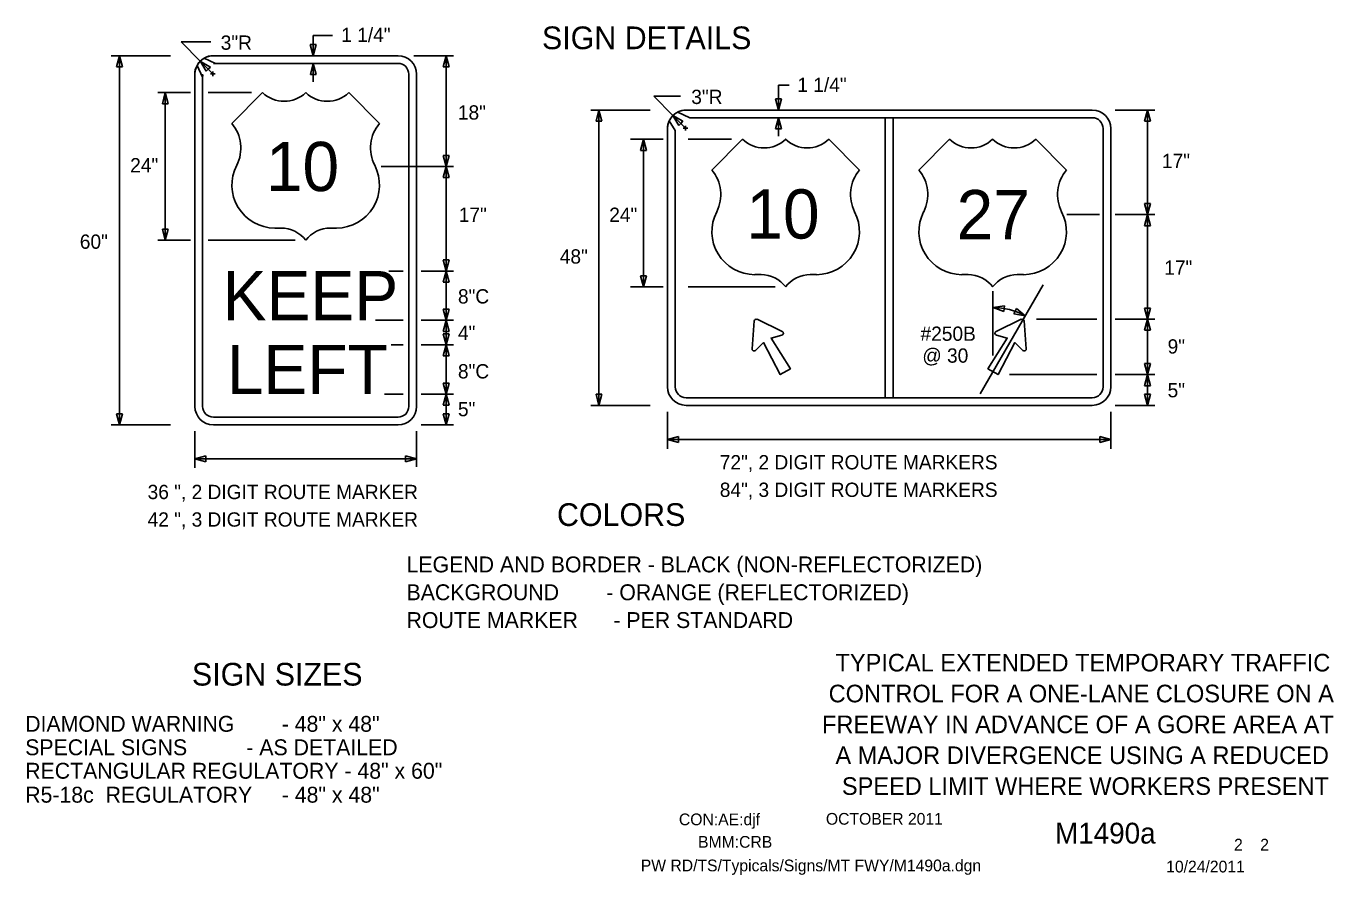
# Model space of a CAD drawing. Extents: x 16284 to 18465, y 5417 to 6974.
# Drawn here: x 17775 to 18465, y 5932 to 6380 of the extents above; entities that cross this region are included whole.
import ezdxf

# ---------------------------------------------------------------- set-up
doc = ezdxf.new("R2010")
doc.units = 0
for name, color, linetype in [('BORDER', 7, 'Continuous'), ('BORDER_SIGNAL_WO', 7, 'Continuous'), ('TRAFFIC_SIGNS_PR', 7, 'Continuous'), ('TYPICAL_EX', 7, 'Continuous'), ('TYPICAL_TEXT_DIMEN_PR', 7, 'Continuous')]:
    doc.layers.add(name, color=color, linetype=linetype)

msp = doc.modelspace()

# ---------------------------------------------------------------- linework, layer by layer
at = {"layer": 'TRAFFIC_SIGNS_PR'}
for p, q in [((17866.33, 6360.97), (17865.33, 6359.46)), ((17865.36, 6359.39), (17868.23, 6353.35)), ((17875.12, 6360.53), (17869.02, 6363.27)), ((17873.92, 6364.59), (17971.42, 6364.59)), ((17971.42, 6360.53), (17873.92, 6360.53)), ((17864.17, 6179.34), (17864.17, 6354.84)), ((17868.23, 6354.84), (17868.23, 6179.34)), ((17977.1, 6179.34), (17977.1, 6354.84)), ((17981.17, 6354.84), (17981.17, 6179.34)), ((18125.39, 6331.84), (18119.16, 6334.86)), ((18123.44, 6335.89), (18337.94, 6335.89)), ((18123.44, 6335.89), (18337.94, 6335.89)), ((18125.38, 6331.83), (18228.66, 6331.83)), ((18337.94, 6331.83), (18125.38, 6331.83)), ((18228.66, 6331.83), (18228.66, 6183.95)), ((18232.72, 6331.83), (18232.72, 6183.95)), ((18232.72, 6331.83), (18337.94, 6331.83)), ((18113.69, 6326.14), (18113.69, 6189.64)), ((18113.69, 6189.64), (18113.69, 6326.14)), ((18114.61, 6330.15), (18117.74, 6325.11)), ((18117.75, 6325.09), (18117.75, 6189.64)), ((18117.75, 6325.09), (18117.75, 6189.64)), ((18343.62, 6326.14), (18343.62, 6280.39)), ((18343.63, 6189.64), (18343.63, 6326.14)), ((18347.69, 6326.14), (18347.69, 6189.64)), ((18347.69, 6326.14), (18347.69, 6189.64)), ((18343.62, 6280.39), (18343.62, 6189.64)), ((18158.29, 6209.75), (18159.44, 6224.47)), ((18160.95, 6225.34), (18174.27, 6218.98)), ((18300.42, 6225.34), (18287.11, 6218.98)), ((18303.08, 6209.75), (18301.94, 6224.47)), ((18123.44, 6183.95), (18337.94, 6183.95)), ((18123.44, 6179.89), (18337.94, 6179.89)), ((18337.94, 6179.89), (18123.44, 6179.89)), ((17873.92, 6173.65), (17971.42, 6173.65)), ((17971.42, 6169.59), (17873.92, 6169.59))]:
    msp.add_line(p, q, dxfattribs=at)
for points in [[(18125.38, 6331.83), (18125.36, 6331.84)], [(18117.74, 6325.11), (18117.75, 6325.09)], [(18174.1, 6217.01), (18168.38, 6215.43), (18178.6, 6199.26), (18173.2, 6196.14), (18164.31, 6213.08), (18160.08, 6208.91)], [(18287.27, 6217.01), (18292.99, 6215.43), (18282.78, 6199.26), (18288.17, 6196.14), (18297.07, 6213.08), (18301.29, 6208.91)]]:
    msp.add_lwpolyline(points, dxfattribs=at)
msp.add_lwpolyline([(18228.66, 6331.83), (18232.72, 6331.83), (18232.72, 6183.95), (18228.66, 6183.95)], close=True, dxfattribs=at)
for centre, radius, start, end in [((17871.2, 6355.43), 7.06, 145.86811, 184.82317), ((17873.92, 6354.84), 9.75, 90, 180), ((17873.33, 6357.01), 7.6, 85.58319, 124.53531), ((17874.52, 6364.95), 4.47, 262.2432, 277.7568), ((17971.42, 6354.84), 9.75, 0, 90), ((17971.42, 6354.84), 5.69, 0, 90), ((17862.77, 6354.1), 5.51, 352.24294, 7.75653), ((18123.44, 6326.14), 9.75, 90, 180), ((18123.44, 6326.14), 9.75, 90, 180), ((18122.76, 6329.33), 6.6, 84.11162, 123.06374), ((18124.38, 6339.01), 7.24, 277.81035, 278.05403), ((18337.94, 6326.14), 9.75, 0, 90), ((18337.94, 6326.14), 9.75, 0, 90), ((18337.94, 6326.14), 5.69, 0, 89.99421), ((18337.94, 6326.14), 5.69, 0, 90), ((18119.82, 6326.85), 6.17, 147.60925, 186.56283), ((18160.5, 6224.38), 1.06, 64.48226, 175.51774), ((18300.88, 6224.38), 1.06, 4.48226, 115.51774), ((18173.81, 6218.02), 1.06, 285.9885, 64.48226), ((18287.56, 6218.02), 1.06, 115.51774, 254.0115), ((18159.35, 6209.67), 1.06, 175.51775, 314.01151), ((18302.03, 6209.67), 1.06, 225.98849, 4.48225), ((18123.44, 6189.64), 9.75, 180, 270), ((18123.44, 6189.64), 9.75, 180, 270), ((18123.44, 6189.64), 5.69, 180, 270), ((18123.44, 6189.64), 5.69, 180, 270), ((18337.94, 6189.64), 9.75, 270, 0), ((18337.94, 6189.64), 5.69, 270, 0), ((18337.94, 6189.64), 9.75, 270, 0), ((18337.94, 6189.64), 5.69, 270, 0), ((17873.92, 6179.34), 9.75, 180, 270), ((17873.92, 6179.34), 5.69, 180, 270), ((17971.42, 6179.34), 5.69, 270, 0), ((17971.42, 6179.34), 9.75, 270, 0)]:
    msp.add_arc(centre, radius, start, end, dxfattribs=at)
at = {"layer": 'TYPICAL_EX'}
for p, q in [((17883.67, 6328.84), (17899.92, 6345.09)), ((17961.67, 6328.84), (17945.42, 6345.09)), ((18137.05, 6304.23), (18153.3, 6320.48)), ((18215.05, 6304.23), (18198.8, 6320.48)), ((18246.33, 6304.23), (18262.58, 6320.48)), ((18324.33, 6304.23), (18308.08, 6320.48)), ((17906.39, 6273.55), (17909.64, 6273.55)), ((17938.94, 6273.55), (17935.69, 6273.55)), ((18159.78, 6248.94), (18163.03, 6248.94)), ((18192.32, 6248.94), (18189.07, 6248.94)), ((18269.05, 6248.94), (18272.3, 6248.94)), ((18301.6, 6248.94), (18298.35, 6248.94))]:
    msp.add_line(p, q, dxfattribs=at)
for centre, radius, start, end in [((17911.29, 6356.93), 16.42, 226.14041, 313.85958), ((17934.04, 6356.93), 16.42, 226.14042, 313.85959), ((17868.26, 6315.83), 20.16, 333.09768, 40.19361), ((17977.07, 6315.83), 20.16, 139.80639, 206.90233), ((18164.68, 6332.32), 16.42, 226.14041, 313.85958), ((18187.42, 6332.32), 16.42, 226.14042, 313.85959), ((18273.95, 6332.32), 16.42, 226.14041, 313.85958), ((18296.7, 6332.32), 16.42, 226.14042, 313.85959), ((17906.43, 6296.27), 22.73, 152.6698, 269.90132), ((17938.9, 6296.27), 22.73, 270.09868, 27.3302), ((18121.65, 6291.22), 20.16, 333.09768, 40.19361), ((18230.45, 6291.22), 20.16, 139.80639, 206.90233), ((18230.93, 6291.22), 20.16, 333.09768, 40.19361), ((18339.73, 6291.22), 20.16, 139.80639, 206.90233), ((18159.82, 6271.66), 22.73, 152.6698, 269.90132), ((18192.28, 6271.66), 22.73, 270.09868, 27.3302), ((18269.09, 6271.66), 22.73, 152.6698, 269.90132), ((18301.56, 6271.66), 22.73, 270.09868, 27.3302), ((17909.68, 6257.27), 16.28, 37.1038, 90.13853), ((17935.65, 6257.27), 16.28, 89.86147, 142.8962), ((18163.07, 6232.66), 16.28, 37.1038, 90.13853), ((18189.03, 6232.66), 16.28, 89.86147, 142.8962), ((18272.35, 6232.66), 16.28, 37.1038, 90.13853), ((18298.31, 6232.66), 16.28, 89.86147, 142.8962)]:
    msp.add_arc(centre, radius, start, end, dxfattribs=at)
at = {"layer": 'TYPICAL_TEXT_DIMEN_PR'}
for p, q in [((17926.64, 6375.35), (17926.64, 6364.59)), ((17926.64, 6375.35), (17936.74, 6375.35)), ((17872.54, 6371.87), (17856.88, 6371.87)), ((17856.88, 6371.87), (17867.12, 6361.64)), ((17926.64, 6364.59), (17925.07, 6370.45)), ((17925.07, 6370.45), (17926.64, 6370.45)), ((17926.64, 6370.45), (17928.21, 6370.45)), ((17928.21, 6370.45), (17926.64, 6364.59)), ((17851.34, 6364.59), (17820.04, 6364.59)), ((17822.81, 6358.73), (17824.38, 6364.59)), ((17824.38, 6358.73), (17822.81, 6358.73)), ((17824.38, 6364.59), (17824.38, 6169.59)), ((17824.38, 6364.59), (17825.95, 6358.73)), ((17825.95, 6358.73), (17824.38, 6358.73)), ((17867.12, 6361.64), (17873.67, 6355.08)), ((17870.15, 6356.38), (17867.12, 6361.64)), ((17867.12, 6361.64), (17872.37, 6358.6)), ((17872.37, 6358.6), (17871.26, 6357.49)), ((17925.12, 6354.67), (17926.69, 6360.53)), ((17926.69, 6360.53), (17926.69, 6350.78)), ((17926.69, 6360.53), (17928.26, 6354.67)), ((17979.71, 6364.59), (18000.67, 6364.59)), ((17995.2, 6358.73), (17996.77, 6364.59)), ((17996.77, 6358.73), (17995.2, 6358.73)), ((17996.77, 6364.59), (17996.77, 6306.09)), ((17996.77, 6364.59), (17998.34, 6358.73)), ((17998.34, 6358.73), (17996.77, 6358.73)), ((17871.26, 6357.49), (17870.15, 6356.38)), ((17872.47, 6355.08), (17874.88, 6355.08)), ((17873.67, 6353.87), (17873.67, 6356.29)), ((17926.69, 6354.67), (17925.12, 6354.67)), ((17928.26, 6354.67), (17926.69, 6354.67)), ((17861.79, 6345.09), (17844.67, 6345.09)), ((17846.99, 6339.23), (17848.56, 6345.09)), ((17848.56, 6345.09), (17848.56, 6267.09)), ((17848.56, 6345.09), (17850.13, 6339.23)), ((17894.03, 6345.09), (17871.16, 6345.09)), ((18172.3, 6349.04), (18172.3, 6335.89)), ((18172.3, 6349.04), (18177.82, 6349.04)), ((17848.56, 6339.23), (17846.99, 6339.23)), ((17850.13, 6339.23), (17848.56, 6339.23)), ((18120.58, 6343.18), (18106.4, 6343.18)), ((18106.4, 6343.18), (18116.55, 6333.03)), ((18172.3, 6335.89), (18170.72, 6341.75)), ((18170.72, 6341.75), (18172.3, 6341.75)), ((18172.3, 6341.75), (18173.87, 6341.75)), ((18173.87, 6341.75), (18172.3, 6335.89)), ((18104.46, 6335.89), (18073.16, 6335.89)), ((18075.93, 6330.03), (18077.5, 6335.89)), ((18077.5, 6335.89), (18077.5, 6179.89)), ((18077.5, 6335.89), (18079.07, 6330.03)), ((18116.55, 6333.03), (18123.2, 6326.38)), ((18119.58, 6327.77), (18116.55, 6333.03)), ((18116.55, 6333.03), (18121.81, 6329.99)), ((18170.77, 6325.97), (18172.34, 6331.83)), ((18170.77, 6325.97), (18172.34, 6331.83)), ((18172.34, 6331.83), (18172.34, 6322.08)), ((18172.34, 6331.83), (18173.92, 6325.97)), ((18172.34, 6331.83), (18173.92, 6325.97)), ((18350.06, 6335.89), (18371.02, 6335.89)), ((18365.55, 6330.03), (18367.12, 6335.89)), ((18367.12, 6335.89), (18367.12, 6280.64)), ((18367.12, 6335.89), (18368.69, 6330.03)), ((18077.5, 6330.03), (18075.93, 6330.03)), ((18079.07, 6330.03), (18077.5, 6330.03)), ((18120.7, 6328.88), (18119.58, 6327.77)), ((18121.81, 6329.99), (18120.7, 6328.88)), ((18121.99, 6326.38), (18124.41, 6326.38)), ((18123.2, 6325.17), (18123.2, 6327.59)), ((18172.34, 6325.97), (18170.77, 6325.97)), ((18172.34, 6325.97), (18170.77, 6325.97)), ((18173.92, 6325.97), (18172.34, 6325.97)), ((18173.92, 6325.97), (18172.34, 6325.97)), ((18367.12, 6330.03), (18365.55, 6330.03)), ((18368.69, 6330.03), (18367.12, 6330.03)), ((18111.31, 6320.48), (18094.19, 6320.48)), ((18099.48, 6314.62), (18101.06, 6320.48)), ((18101.06, 6320.48), (18101.06, 6242.48)), ((18101.06, 6320.48), (18102.63, 6314.62)), ((18147.42, 6320.48), (18124.54, 6320.48)), ((17996.77, 6306.09), (17995.2, 6311.95)), ((17995.2, 6311.95), (17996.77, 6311.95)), ((17996.77, 6311.95), (17998.34, 6311.95)), ((17998.34, 6311.95), (17996.77, 6306.09)), ((18101.06, 6314.62), (18099.48, 6314.62)), ((18102.63, 6314.62), (18101.06, 6314.62)), ((17962.56, 6306.09), (18000.67, 6306.09)), ((17995.2, 6300.23), (17996.77, 6306.09)), ((17996.77, 6306.09), (17996.77, 6250.84)), ((17996.77, 6306.09), (17998.34, 6300.23)), ((17996.77, 6300.23), (17995.2, 6300.23)), ((17998.34, 6300.23), (17996.77, 6300.23)), ((18367.12, 6280.64), (18365.55, 6286.5)), ((18365.55, 6286.5), (18367.12, 6286.5)), ((18367.12, 6286.5), (18368.69, 6286.5)), ((18368.69, 6286.5), (18367.12, 6280.64)), ((18324.5, 6280.64), (18341.65, 6280.64)), ((18350.06, 6280.64), (18371.02, 6280.64)), ((18365.55, 6274.78), (18367.12, 6280.64)), ((18367.12, 6280.64), (18367.12, 6225.39)), ((18367.12, 6280.64), (18368.69, 6274.78)), ((17848.56, 6267.09), (17846.99, 6272.95)), ((17846.99, 6272.95), (17848.56, 6272.95)), ((17848.56, 6272.95), (17850.13, 6272.95)), ((17850.13, 6272.95), (17848.56, 6267.09)), ((18367.12, 6274.78), (18365.55, 6274.78)), ((18368.69, 6274.78), (18367.12, 6274.78)), ((17861.79, 6267.09), (17844.67, 6267.09)), ((17917.16, 6267.09), (17871.16, 6267.09)), ((17996.77, 6250.84), (17995.2, 6256.7)), ((17995.2, 6256.7), (17996.77, 6256.7)), ((17996.77, 6256.7), (17998.34, 6256.7)), ((17998.34, 6256.7), (17996.77, 6250.84)), ((17966.49, 6250.84), (17974.17, 6250.84)), ((17983.54, 6250.84), (18000.67, 6250.84)), ((17995.2, 6244.98), (17996.77, 6250.84)), ((17996.77, 6250.84), (17996.77, 6224.84)), ((17996.77, 6250.84), (17998.34, 6244.98)), ((18101.06, 6242.48), (18099.48, 6248.34)), ((18099.48, 6248.34), (18101.06, 6248.34)), ((18101.06, 6248.34), (18102.63, 6248.34)), ((18102.63, 6248.34), (18101.06, 6242.48)), ((17996.77, 6244.98), (17995.2, 6244.98)), ((17998.34, 6244.98), (17996.77, 6244.98)), ((18111.31, 6242.48), (18094.19, 6242.48)), ((18170.54, 6242.48), (18124.54, 6242.48)), ((18278.72, 6185.99), (18311.96, 6243.58)), ((18285.48, 6206.15), (18285.48, 6240.14)), ((17996.77, 6224.84), (17995.2, 6230.7)), ((17995.2, 6230.7), (17996.77, 6230.7)), ((17996.77, 6230.7), (17998.34, 6230.7)), ((17998.34, 6230.7), (17996.77, 6224.84)), ((18285.51, 6231.59), (18291.5, 6232.55)), ((18291.17, 6229.42), (18285.51, 6231.59)), ((18291.34, 6230.98), (18291.17, 6229.42)), ((18291.5, 6232.55), (18291.34, 6230.98)), ((18296.49, 6228.26), (18297.17, 6229.68)), ((18302.46, 6227.13), (18296.49, 6228.26)), ((18297.17, 6229.68), (18297.86, 6231.09)), ((18297.86, 6231.09), (18302.46, 6227.13)), ((18367.12, 6225.39), (18365.55, 6231.25)), ((18365.55, 6231.25), (18367.12, 6231.25)), ((18367.12, 6231.25), (18368.69, 6231.25)), ((18368.69, 6231.25), (18367.12, 6225.39)), ((17959.48, 6224.84), (17974.17, 6224.84)), ((17983.54, 6224.84), (18000.67, 6224.84)), ((17995.2, 6218.98), (17996.77, 6224.84)), ((17996.77, 6224.84), (17996.77, 6211.84)), ((17996.77, 6224.84), (17998.34, 6218.98)), ((18308.43, 6225.39), (18340.3, 6225.39)), ((18350.06, 6225.39), (18371.02, 6225.39)), ((18365.55, 6219.53), (18367.12, 6225.39)), ((18367.12, 6225.39), (18367.12, 6196.14)), ((18367.12, 6225.39), (18368.69, 6219.53)), ((17996.77, 6218.98), (17995.2, 6218.98)), ((17996.77, 6211.84), (17995.2, 6217.7)), ((17995.2, 6217.7), (17996.77, 6217.7)), ((17998.34, 6218.98), (17996.77, 6218.98)), ((17996.77, 6217.7), (17998.34, 6217.7)), ((17998.34, 6217.7), (17996.77, 6211.84)), ((18367.12, 6219.53), (18365.55, 6219.53)), ((18368.69, 6219.53), (18367.12, 6219.53)), ((17967.83, 6211.84), (17974.17, 6211.84)), ((17983.54, 6211.84), (18000.67, 6211.84)), ((17995.2, 6205.98), (17996.77, 6211.84)), ((17996.77, 6211.84), (17996.77, 6185.84)), ((17996.77, 6211.84), (17998.34, 6205.98)), ((17996.77, 6205.98), (17995.2, 6205.98)), ((17998.34, 6205.98), (17996.77, 6205.98)), ((18367.12, 6196.14), (18365.55, 6202)), ((18365.55, 6202), (18367.12, 6202)), ((18367.12, 6202), (18368.69, 6202)), ((18368.69, 6202), (18367.12, 6196.14)), ((18294.29, 6196.14), (18340.3, 6196.14)), ((18350.06, 6196.14), (18371.02, 6196.14)), ((18365.55, 6190.28), (18367.12, 6196.14)), ((18367.12, 6196.14), (18367.12, 6179.89)), ((18367.12, 6196.14), (18368.69, 6190.28)), ((17964.33, 6185.84), (17974.17, 6185.84)), ((17983.54, 6185.84), (18000.67, 6185.84)), ((17996.77, 6185.84), (17995.2, 6191.7)), ((17995.2, 6191.7), (17996.77, 6191.7)), ((17995.2, 6179.98), (17996.77, 6185.84)), ((17996.77, 6191.7), (17998.34, 6191.7)), ((17998.34, 6191.7), (17996.77, 6185.84)), ((17996.77, 6185.84), (17996.77, 6169.59)), ((17996.77, 6185.84), (17998.34, 6179.98)), ((18077.5, 6179.89), (18075.93, 6185.75)), ((18075.93, 6185.75), (18077.5, 6185.75)), ((18077.5, 6185.75), (18079.07, 6185.75)), ((18079.07, 6185.75), (18077.5, 6179.89)), ((18367.12, 6190.28), (18365.55, 6190.28)), ((18367.12, 6179.89), (18365.55, 6185.75)), ((18365.55, 6185.75), (18367.12, 6185.75)), ((18368.69, 6190.28), (18367.12, 6190.28)), ((18367.12, 6185.75), (18368.69, 6185.75)), ((18368.69, 6185.75), (18367.12, 6179.89)), ((17996.77, 6179.98), (17995.2, 6179.98)), ((17998.34, 6179.98), (17996.77, 6179.98)), ((18104.46, 6179.89), (18073.16, 6179.89)), ((18350.06, 6179.89), (18367.19, 6179.89)), ((18350.06, 6179.89), (18371.02, 6179.89)), ((18350.06, 6179.89), (18367.19, 6179.89)), ((17824.38, 6169.59), (17822.81, 6175.45)), ((17822.81, 6175.45), (17824.38, 6175.45)), ((17824.38, 6175.45), (17825.95, 6175.45)), ((17825.95, 6175.45), (17824.38, 6169.59)), ((17996.77, 6169.59), (17995.2, 6175.45)), ((17995.2, 6175.45), (17996.77, 6175.45)), ((17996.77, 6175.45), (17998.34, 6175.45)), ((17998.34, 6175.45), (17996.77, 6169.59)), ((18113.69, 6176.55), (18113.69, 6156.99)), ((18347.69, 6176.55), (18347.69, 6156.99)), ((17851.34, 6169.59), (17820.04, 6169.59)), ((17864.17, 6166.25), (17864.17, 6146.89)), ((17981.17, 6166.25), (17981.17, 6147.35)), ((17983.54, 6169.59), (18000.67, 6169.59)), ((18113.69, 6161.92), (18119.55, 6163.49)), ((18113.69, 6161.92), (18347.69, 6161.92)), ((18119.55, 6160.35), (18113.69, 6161.92)), ((18119.55, 6163.49), (18119.55, 6161.92)), ((18119.55, 6161.92), (18119.55, 6160.35)), ((18341.83, 6161.92), (18341.83, 6163.49)), ((18341.83, 6163.49), (18347.69, 6161.92)), ((18347.69, 6161.92), (18341.83, 6160.35)), ((18341.83, 6160.35), (18341.83, 6161.92)), ((17864.17, 6151.62), (17870.03, 6153.19)), ((17864.17, 6151.62), (17981.17, 6151.62)), ((17870.03, 6150.05), (17864.17, 6151.62)), ((17870.03, 6153.19), (17870.03, 6151.62)), ((17870.03, 6151.62), (17870.03, 6150.05)), ((17975.3, 6151.62), (17975.3, 6153.19)), ((17975.3, 6153.19), (17981.17, 6151.62)), ((17981.17, 6151.62), (17975.3, 6150.05)), ((17975.3, 6150.05), (17975.3, 6151.62))]:
    msp.add_line(p, q, dxfattribs=at)
msp.add_arc((18285.67, 6197.15), 34.39, 60.74521, 90.32117, dxfattribs=at)

# ---------------------------------------------------------------- texts
at = {"layer": 'BORDER'}
for s, p in [('TYPICAL EXTENDED TEMPORARY TRAFFIC', (18202.37, 6039.3)), ('CONTROL FOR A ONE-LANE CLOSURE ON A', (18198.74, 6023)), ('FREEWAY IN ADVANCE OF A GORE AREA AT', (18195.24, 6006.7)), ('A MAJOR DIVERGENCE USING A REDUCED', (18202.34, 5990.4)), ('SPEED LIMIT WHERE WORKERS PRESENT', (18205.74, 5974.11))]:
    msp.add_text(s, height=9.3, dxfattribs=at).set_placement(p)
at = {"layer": 'BORDER_SIGNAL_WO'}
for s, height, p in [('CON:AE:djf  ', 6.2, (18119.69, 5958.06)), ('    OCTOBER 2011    ', 6.2, (18188.08, 5958.34)), ('    M1490a   ', 11, (18301.86, 5948.38)), ('BMM:CRB   ', 6.2, (18129.81, 5946.17)), (' 2    2 ', 6.2, (18410.45, 5944.7)), ('PW RD/TS/Typicals/Signs/MT FWY/M1490a.dgn      ', 6.2, (18099.55, 5933.71)), ('10/24/2011    ', 6.2, (18376.93, 5933.13))]:
    msp.add_text(s, height=height, dxfattribs=at).set_placement(p)
at = {"layer": 'TRAFFIC_SIGNS_PR'}
for s, p in [('10', (17901.64, 6293.09)), ('10', (18155.29, 6268.02)), ('27', (18266.29, 6267.66)), ('KEEP', (17878.77, 6224.84)), ('LEFT', (17881, 6185.84))]:
    msp.add_text(s, height=26, dxfattribs=at).set_placement(p)
at = {"layer": 'TYPICAL_TEXT_DIMEN_PR'}
for s, height, p in [('1 1/4"', 7.55, (17941.44, 6371.85)), ('SIGN DETAILS', 12, (18047.39, 6368.06)), ('3"R', 7.55, (17877.8, 6367.75)), ('1 1/4"', 7.55, (18182.22, 6345.47)), ('3"R', 7.55, (18126.22, 6339.1)), ('18"', 7.55, (18003.01, 6330.86)), ('24"', 7.55, (17830.01, 6302.97)), ('17"', 7.55, (18374.7, 6305.25)), ('17"', 7.55, (18003.46, 6276.81)), ('24"', 7.55, (18082.91, 6276.81)), ('60"', 7.55, (17803.41, 6262.61)), ('48"', 7.55, (18056.8, 6254.79)), ('17"', 7.55, (18375.9, 6248.89)), ('8"C', 7.55, (18003.04, 6233.7)), ('4" ', 7.55, (18003.04, 6214.44)), ('#250B', 7.55, (18247.25, 6213.98)), ('9"', 7.55, (18377.68, 6207.24)), ('@ 30', 7.55, (18248.19, 6202.43)), ('8"C', 7.55, (18003.04, 6194.11)), ('5"', 7.55, (18377.68, 6184.14)), ('5" ', 7.55, (18003.04, 6174.14)), ('72", 2 DIGIT ROUTE MARKERS', 7.55, (18141.27, 6146.06)), ('36 ", 2 DIGIT ROUTE MARKER', 7.55, (17839.21, 6130.36)), ('84", 3 DIGIT ROUTE MARKERS', 7.55, (18141.27, 6131.51)), ('42 ", 3 DIGIT ROUTE MARKER', 7.55, (17839.21, 6115.81)), ('COLORS', 12, (18055.33, 6116.17)), ('LEGEND AND BORDER - BLACK (NON-REFLECTORIZED)', 8.4, (17975.9, 6091.65)), ('BACKGROUND        - ORANGE (REFLECTORIZED)', 8.4, (17975.9, 6076.94)), ('ROUTE MARKER      - PER STANDARD', 8.4, (17975.9, 6062.24)), ('SIGN SIZES', 12, (17862.62, 6031.84)), ('DIAMOND WARNING        - 48" x 48"', 8.4, (17774.58, 6007.44)), ('SPECIAL SIGNS          - AS DETAILED', 8.4, (17774.58, 5995.04)), ('RECTANGULAR REGULATORY - 48" x 60"', 8.4, (17774.58, 5982.64)), ('R5-18c  REGULATORY     - 48" x 48"', 8.4, (17774.58, 5969.99))]:
    msp.add_text(s, height=height, dxfattribs=at).set_placement(p)

doc.saveas('drawing.dxf')
